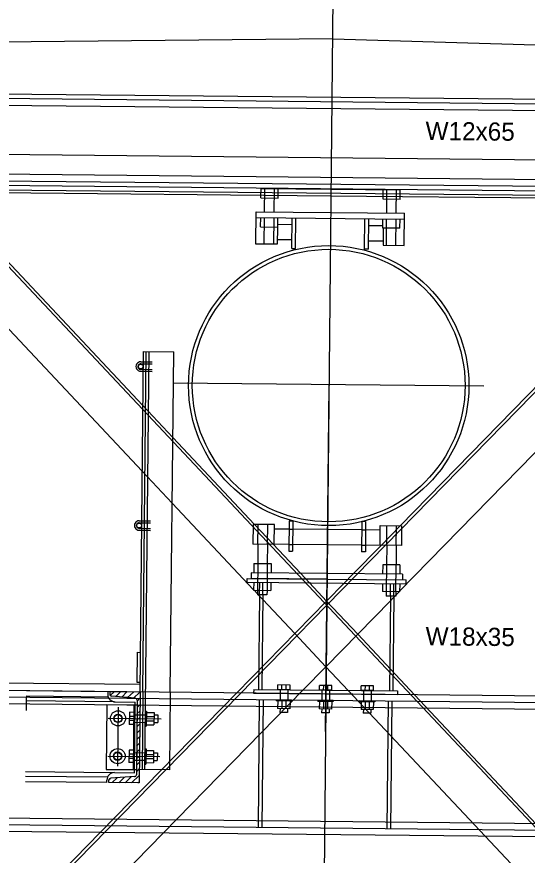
# Model space of a CAD drawing. Extents: x 632312 to 632885, y 378199 to 378534.
# Drawn here: x 632395.47 to 632401.08, y 378386.51 to 378395.75 of the extents above; entities that cross this region are included whole.
import ezdxf

# ---------------------------------------------------------------- set-up
doc = ezdxf.new("R2010")
doc.units = 0
for name, color, linetype in [('B_Boring', 7, 'Continuous'), ('B_Boring Annot', 7, 'Continuous'), ('R_Proposed Const Limits', 7, 'Continuous'), ('R_Proposed Const Limits Cut', 7, 'Continuous'), ('R_Road Edge of Shoulder', 7, 'Continuous'), ('R_Wall', 7, 'Continuous'), ('SHT_Dimensions', 7, 'Continuous')]:
    doc.layers.add(name, color=color, linetype=linetype)

msp = doc.modelspace()

# ---------------------------------------------------------------- linework, layer by layer
at = {"layer": 'B_Boring'}
for p, q in [((632404.4301, 378394.7533), (632393.4306, 378394.8626)), ((632404.4306, 378394.8037), (632393.4311, 378394.913)), ((632404.421, 378393.8458), (632393.4216, 378393.9552)), ((632404.4205, 378393.7954), (632393.4211, 378393.9048)), ((632398.1539, 378393.7504), (632398.1549, 378393.8577)), ((632399.6866, 378393.8352), (632398.1549, 378393.8505)), ((632398.1945, 378393.5973), (632398.1971, 378393.8573)), ((632398.2993, 378393.5962), (632398.3019, 378393.8562)), ((632398.343, 378393.7485), (632398.3441, 378393.8558)), ((632394.3786, 378393.8192), (632398.9201, 378393.7741)), ((632398.9201, 378393.7741), (632403.4615, 378393.7289)), ((632399.4965, 378393.737), (632399.4975, 378393.8443)), ((632399.5371, 378393.5839), (632399.5397, 378393.8439)), ((632399.6419, 378393.5829), (632399.6445, 378393.8429)), ((632399.6856, 378393.7351), (632399.6867, 378393.8425)), ((632398.1539, 378393.7504), (632398.343, 378393.7485)), ((632399.6856, 378393.7351), (632399.4965, 378393.737)), ((632398.0985, 378393.2433), (632398.102, 378393.5982)), ((632398.102, 378393.5982), (632399.7345, 378393.582)), ((632399.7309, 378393.2271), (632399.7345, 378393.582)), ((632398.1014, 378393.535), (632399.7338, 378393.5188)), ((632398.1507, 378393.4324), (632398.1517, 378393.5345)), ((632398.191, 378393.2424), (632398.1939, 378393.5341)), ((632398.2958, 378393.2413), (632398.2987, 378393.533)), ((632398.3399, 378393.4305), (632398.3409, 378393.5326)), ((632398.4929, 378393.1953), (632398.4963, 378393.5311)), ((632398.534, 378393.1949), (632398.5373, 378393.5307)), ((632399.2945, 378393.1873), (632399.2978, 378393.5231)), ((632399.3356, 378393.1869), (632399.3389, 378393.5227)), ((632399.4933, 378393.419), (632399.4943, 378393.5212)), ((632399.5336, 378393.229), (632399.5365, 378393.5207)), ((632399.6384, 378393.228), (632399.6413, 378393.5197)), ((632399.6825, 378393.4171), (632399.6835, 378393.5193)), ((632398.1507, 378393.4324), (632398.3399, 378393.4305)), ((632398.3345, 378393.4305), (632398.3326, 378393.241)), ((632398.4955, 378393.4561), (632398.3401, 378393.4577)), ((632399.3382, 378393.4478), (632399.4936, 378393.4462)), ((632399.6825, 378393.4171), (632399.4933, 378393.419)), ((632399.4987, 378393.419), (632399.4968, 378393.2294)), ((632398.3326, 378393.241), (632398.0985, 378393.2433)), ((632398.4939, 378393.2882), (632398.3331, 378393.2898)), ((632399.3365, 378393.2798), (632399.4973, 378393.2782)), ((632399.4968, 378393.2294), (632399.7309, 378393.2271)), ((632398.4929, 378393.1953), (632398.534, 378393.1949)), ((632399.3356, 378393.1869), (632399.2945, 378393.1873)), ((632396.824, 378388.3108), (632396.8613, 378392.0606)), ((632396.8552, 378388.3105), (632396.8925, 378392.0603)), ((632396.8613, 378392.0606), (632397.1946, 378392.0573)), ((632397.1573, 378388.3075), (632397.1946, 378392.0573)), ((632396.8323, 378391.9255), (632396.9573, 378391.9243)), ((632396.8325, 378391.9463), (632396.9575, 378391.9451)), ((632396.8314, 378391.8422), (632396.9564, 378391.8409)), ((632396.8316, 378391.863), (632396.9566, 378391.8618)), ((632398.0678, 378390.1571), (632398.0656, 378389.9404)), ((632398.3019, 378390.1548), (632398.0678, 378390.1571)), ((632398.2998, 378389.938), (632398.3019, 378390.1548)), ((632398.4631, 378390.1973), (632398.4598, 378389.8615)), ((632398.4631, 378390.1973), (632398.5042, 378390.1969)), ((632398.5042, 378390.1969), (632398.5009, 378389.8611)), ((632399.2647, 378390.1893), (632399.2614, 378389.8535)), ((632399.3058, 378390.1889), (632399.2647, 378390.1893)), ((632399.3058, 378390.1889), (632399.3024, 378389.8531)), ((632398.4622, 378390.1044), (632398.3014, 378390.106)), ((632399.2638, 378390.0965), (632398.5033, 378390.104)), ((632399.4656, 378390.0944), (632399.3048, 378390.096)), ((632399.464, 378389.9265), (632399.4661, 378390.1432)), ((632399.4661, 378390.1432), (632399.7002, 378390.1409)), ((632399.7002, 378390.1409), (632399.6981, 378389.9241)), ((632398.4605, 378389.9364), (632398.0656, 378389.9404)), ((632398.1212, 378389.9398), (632398.119, 378389.7263)), ((632398.226, 378389.9388), (632398.2238, 378389.7253)), ((632399.2621, 378389.9285), (632398.5016, 378389.936)), ((632399.6981, 378389.9241), (632399.3032, 378389.9281)), ((632399.5378, 378389.9257), (632399.5356, 378389.7122)), ((632399.6426, 378389.9247), (632399.6404, 378389.7112)), ((632398.4598, 378389.8615), (632398.5009, 378389.8611)), ((632399.3024, 378389.8531), (632399.2614, 378389.8535)), ((632398.0768, 378389.7267), (632398.0758, 378389.6246)), ((632398.0768, 378389.7267), (632398.266, 378389.7248)), ((632398.266, 378389.7248), (632398.265, 378389.6227)), ((632399.4934, 378389.7126), (632399.4924, 378389.6105)), ((632399.6826, 378389.7108), (632399.4934, 378389.7126)), ((632399.6826, 378389.7108), (632399.6816, 378389.6086)), ((632398.0454, 378389.6249), (632398.0448, 378389.5617)), ((632399.712, 378389.6083), (632398.0454, 378389.6249)), ((632399.712, 378389.6083), (632399.7114, 378389.5451)), ((632398.0027, 378389.5205), (632398.0031, 378389.5622)), ((632398.0027, 378389.5205), (632399.7526, 378389.5031)), ((632398.0031, 378389.5621), (632399.753, 378389.5447)), ((632398.0748, 378389.5197), (632398.0739, 378389.4317)), ((632398.264, 378389.5179), (632398.2631, 378389.4298)), ((632399.7526, 378389.5031), (632399.753, 378389.5448)), ((632398.0739, 378389.4317), (632398.2631, 378389.4298)), ((632398.1161, 378389.4313), (632398.1156, 378389.3823)), ((632398.2209, 378389.4302), (632398.2204, 378389.3812)), ((632399.4914, 378389.5057), (632399.4905, 378389.4176)), ((632399.6797, 378389.4157), (632399.4905, 378389.4176)), ((632399.5327, 378389.4172), (632399.5322, 378389.3682)), ((632399.6375, 378389.4162), (632399.637, 378389.3671)), ((632399.6806, 378389.5038), (632399.6797, 378389.4157)), ((632398.2204, 378389.3812), (632398.1156, 378389.3823)), ((632398.1388, 378389.382), (632398.1285, 378388.3395)), ((632398.1743, 378389.3817), (632398.1639, 378388.3392)), ((632399.637, 378389.3671), (632399.5322, 378389.3682)), ((632399.5784, 378389.3677), (632399.568, 378388.3252)), ((632399.6138, 378389.3674), (632399.6034, 378388.3249)), ((632396.7938, 378388.4153), (632396.7971, 378388.7486)), ((632396.7971, 378388.7486), (632396.8283, 378388.7483)), ((632396.8248, 378388.3942), (632394.3249, 378388.419)), ((632396.825, 378388.415), (632396.7938, 378388.4153)), ((632404.3653, 378388.2359), (632393.3658, 378388.3452)), ((632396.4692, 378388.3144), (632395.5741, 378388.3233)), ((632396.4692, 378388.3144), (632396.4689, 378388.2873)), ((632396.4907, 378388.3141), (632396.4904, 378388.287)), ((632396.824, 378388.3108), (632396.4907, 378388.3141)), ((632396.4964, 378388.2722), (632396.5387, 378388.3137)), ((632396.5573, 378388.2619), (632396.6094, 378388.313)), ((632396.6227, 378388.256), (632396.6801, 378388.3123)), ((632396.6881, 378388.2501), (632396.7508, 378388.3116)), ((632396.7535, 378388.2442), (632396.8215, 378388.3109)), ((632396.824, 378388.3108), (632396.814, 378387.3109)), ((632398.0743, 378388.3401), (632398.0739, 378388.2984)), ((632398.0743, 378388.3401), (632399.6576, 378388.3243)), ((632398.3399, 378388.3374), (632398.3405, 378388.3895)), ((632398.4753, 378388.3361), (632398.3399, 378388.3374)), ((632398.4759, 378388.3882), (632398.3405, 378388.3895)), ((632398.366, 378388.3372), (632398.3648, 378388.223)), ((632398.3851, 378388.337), (632398.3856, 378388.3891)), ((632398.4302, 378388.3365), (632398.4307, 378388.3886)), ((632398.4493, 378388.3363), (632398.4482, 378388.2222)), ((632398.4753, 378388.3361), (632398.4759, 378388.3882)), ((632398.7983, 378388.3329), (632398.7988, 378388.3849)), ((632398.9336, 378388.3315), (632398.7983, 378388.3329)), ((632398.9342, 378388.3836), (632398.7988, 378388.3849)), ((632398.8243, 378388.3326), (632398.8231, 378388.2184)), ((632398.8434, 378388.3324), (632398.8439, 378388.3845)), ((632398.8885, 378388.332), (632398.889, 378388.3841)), ((632398.9076, 378388.3318), (632398.9065, 378388.2176)), ((632398.9336, 378388.3315), (632398.9342, 378388.3836)), ((632399.2566, 378388.3283), (632399.2571, 378388.3804)), ((632399.392, 378388.327), (632399.2566, 378388.3283)), ((632399.3925, 378388.379), (632399.2571, 378388.3804)), ((632399.2826, 378388.3281), (632399.2815, 378388.2139)), ((632399.3017, 378388.3279), (632399.3022, 378388.3799)), ((632399.3468, 378388.3274), (632399.3473, 378388.3795)), ((632399.3659, 378388.3272), (632399.3648, 378388.2131)), ((632399.392, 378388.327), (632399.3925, 378388.379)), ((632399.6576, 378388.3243), (632399.6571, 378388.2826)), ((632404.3645, 378388.1634), (632393.3651, 378388.2727)), ((632395.5733, 378388.2508), (632395.5719, 378388.1065)), ((632396.4747, 378388.256), (632395.5735, 378388.2649)), ((632396.7716, 378388.2426), (632396.511, 378388.266)), ((632396.7922, 378388.2216), (632396.7841, 378387.4007)), ((632396.7922, 378388.2121), (632396.8233, 378388.2426)), ((632398.0739, 378388.2984), (632399.6571, 378388.2827)), ((632398.3232, 378388.2234), (632398.3231, 378388.213)), ((632398.4898, 378388.2218), (632398.3232, 378388.2234)), ((632398.4898, 378388.2218), (632398.4897, 378388.2113)), ((632398.7815, 378388.2189), (632398.7814, 378388.2084)), ((632398.9481, 378388.2172), (632398.7815, 378388.2189)), ((632398.9481, 378388.2172), (632398.948, 378388.2068)), ((632396.4584, 378388.1686), (632396.4513, 378387.4603)), ((632396.7917, 378388.1653), (632396.4584, 378388.1686)), ((632396.5514, 378388.2031), (632396.7712, 378388.2009)), ((632396.7534, 378387.4573), (632396.7605, 378388.1656)), ((632396.7635, 378387.4218), (632396.7712, 378388.2009)), ((632396.7917, 378388.1653), (632396.7846, 378387.457)), ((632396.7914, 378388.1413), (632396.8226, 378388.1719)), ((632398.4897, 378388.2113), (632398.3231, 378388.213)), ((632398.3387, 378388.2128), (632398.3379, 378388.1295)), ((632398.4733, 378388.1282), (632398.3379, 378388.1295)), ((632398.3639, 378388.1293), (632398.3635, 378388.0876)), ((632398.3838, 378388.2124), (632398.383, 378388.1291)), ((632398.429, 378388.212), (632398.4281, 378388.1286)), ((632398.4472, 378388.1284), (632398.4468, 378388.0868)), ((632398.4741, 378388.2115), (632398.4733, 378388.1282)), ((632398.948, 378388.2068), (632398.7814, 378388.2084)), ((632398.797, 378388.2083), (632398.7962, 378388.125)), ((632398.9316, 378388.1236), (632398.7962, 378388.125)), ((632398.8222, 378388.1247), (632398.8218, 378388.083)), ((632398.8421, 378388.2078), (632398.8413, 378388.1245)), ((632398.8873, 378388.2074), (632398.8864, 378388.1241)), ((632398.9055, 378388.1239), (632398.9051, 378388.0822)), ((632398.9324, 378388.2069), (632398.9316, 378388.1236)), ((632399.2398, 378388.2143), (632399.2397, 378388.2039)), ((632399.4063, 378388.2022), (632399.2397, 378388.2039)), ((632399.4065, 378388.2126), (632399.2398, 378388.2143)), ((632399.2553, 378388.2037), (632399.2545, 378388.1204)), ((632399.3005, 378388.2033), (632399.2996, 378388.12)), ((632399.3456, 378388.2028), (632399.3448, 378388.1195)), ((632399.3907, 378388.2024), (632399.3899, 378388.1191)), ((632399.4065, 378388.2126), (632399.4063, 378388.2022)), ((632396.7076, 378388.088), (632396.7063, 378387.9526)), ((632396.7593, 378388.0424), (632396.7072, 378388.0429)), ((632396.7597, 378388.0875), (632396.7076, 378388.088)), ((632396.7597, 378388.0875), (632396.7584, 378387.9521)), ((632396.7907, 378388.0706), (632396.8219, 378388.1012)), ((632396.8844, 378388.1019), (632396.8827, 378387.9352)), ((632396.8844, 378388.1019), (632396.8948, 378388.1018)), ((632396.8948, 378388.1018), (632396.8932, 378387.9351)), ((632396.8942, 378388.041), (632396.9775, 378388.0402)), ((632396.8947, 378388.0861), (632396.978, 378388.0853)), ((632396.978, 378388.0853), (632396.9766, 378387.9499)), ((632396.9777, 378388.0593), (632397.0194, 378388.0589)), ((632397.0194, 378388.0589), (632397.0186, 378387.9755)), ((632398.4468, 378388.0868), (632398.3635, 378388.0876)), ((632398.9051, 378388.0822), (632398.8218, 378388.083)), ((632399.3899, 378388.1191), (632399.2545, 378388.1204)), ((632399.2805, 378388.1201), (632399.2801, 378388.0785)), ((632399.3634, 378388.0777), (632399.2801, 378388.0785)), ((632399.3639, 378388.1193), (632399.3634, 378388.0777)), ((632396.7584, 378387.9521), (632396.7063, 378387.9526)), ((632396.7588, 378387.9972), (632396.7067, 378387.9977)), ((632396.7893, 378387.9292), (632396.8205, 378387.9598)), ((632396.79, 378387.9999), (632396.8212, 378388.0305)), ((632396.8933, 378387.9508), (632396.9766, 378387.9499)), ((632396.8938, 378387.9959), (632396.9771, 378387.9951)), ((632396.9769, 378387.976), (632397.0186, 378387.9755)), ((632396.7886, 378387.8585), (632396.8198, 378387.889)), ((632396.8827, 378387.9352), (632396.8932, 378387.9351)), ((632396.7879, 378387.7878), (632396.8191, 378387.8183)), ((632396.7035, 378387.6714), (632396.7021, 378387.536)), ((632396.7556, 378387.6708), (632396.7035, 378387.6714)), ((632396.7556, 378387.6708), (632396.7542, 378387.5355)), ((632396.7865, 378387.6464), (632396.8177, 378387.6769)), ((632396.7872, 378387.7171), (632396.8184, 378387.7476)), ((632396.8803, 378387.6852), (632396.8786, 378387.5186)), ((632396.8803, 378387.6852), (632396.8907, 378387.6851)), ((632396.8907, 378387.6851), (632396.889, 378387.5185)), ((632396.8905, 378387.6695), (632396.9738, 378387.6687)), ((632396.9738, 378387.6687), (632396.9725, 378387.5333)), ((632396.7547, 378387.5806), (632396.7026, 378387.5811)), ((632396.7551, 378387.6257), (632396.703, 378387.6262)), ((632396.7858, 378387.5757), (632396.817, 378387.6062)), ((632396.8896, 378387.5792), (632396.9729, 378387.5784)), ((632396.8901, 378387.6244), (632396.9734, 378387.6235)), ((632396.9736, 378387.6426), (632397.0152, 378387.6422)), ((632397.0152, 378387.6422), (632397.0144, 378387.5589)), ((632396.7542, 378387.5355), (632396.7021, 378387.536)), ((632396.7851, 378387.505), (632396.8163, 378387.5355)), ((632396.8786, 378387.5186), (632396.889, 378387.5185)), ((632396.8892, 378387.5341), (632396.9725, 378387.5333)), ((632396.9728, 378387.5593), (632397.0144, 378387.5589)), ((632396.4513, 378387.4603), (632396.7847, 378387.457)), ((632396.5437, 378387.424), (632396.7635, 378387.4218)), ((632396.7308, 378387.3117), (632396.8149, 378387.3941)), ((632396.7844, 378387.4343), (632396.8156, 378387.4648)), ((632396.4593, 378387.3144), (632395.5641, 378387.3233)), ((632396.4659, 378387.3727), (632395.5647, 378387.3816)), ((632396.4593, 378387.3144), (632396.4595, 378387.3415)), ((632396.4807, 378387.3142), (632396.481, 378387.3413)), ((632396.814, 378387.3109), (632396.4807, 378387.3142)), ((632396.814, 378387.3109), (632396.4807, 378387.3142)), ((632396.4822, 378387.348), (632396.4952, 378387.3608)), ((632396.7631, 378387.3801), (632396.502, 378387.3619)), ((632396.5187, 378387.3138), (632396.5728, 378387.3668)), ((632396.5894, 378387.3131), (632396.6497, 378387.3722)), ((632396.6601, 378387.3124), (632396.7266, 378387.3776)), ((632396.8015, 378387.311), (632396.8142, 378387.3234)), ((632396.8109, 378387.3109), (632396.8141, 378387.314)), ((632404.3506, 378386.7584), (632393.3511, 378386.8678)), ((632404.3499, 378386.6859), (632393.3504, 378386.7953))]:
    msp.add_line(p, q, dxfattribs=at)
for points in [[(632396.8481, 378390.7422), (632394.3742, 378393.378), (632394.7388, 378393.7202), (632396.8553, 378391.4652)], [(632399.6797, 378389.4202), (632403.4571, 378393.2877), (632403.0994, 378393.6371), (632399.6849, 378390.1411)], [(632397.1852, 378391.1137), (632398.0831, 378390.157)], [(632398.074, 378389.4362), (632397.178, 378390.3908)], [(632398.2886, 378389.9381), (632398.5876, 378389.6195)], [(632399.4752, 378389.9263), (632399.1598, 378389.6034)], [(632399.0684, 378389.5099), (632398.8757, 378389.3126), (632397.887, 378388.3003)], [(632398.687, 378389.5137), (632398.8757, 378389.3126)], [(632398.1157, 378389.3917), (632398.0782, 378389.4317)], [(632399.6371, 378389.3766), (632399.6754, 378389.4158)], [(632398.1387, 378389.3672), (632398.1246, 378389.3822)], [(632398.526, 378388.9545), (632398.1737, 378389.3298)], [(632399.6136, 378389.3525), (632399.628, 378389.3672)], [(632398.6195, 378388.3346), (632398.8685, 378388.5896), (632399.5778, 378389.3159)], [(632399.2182, 378388.9476), (632399.8441, 378388.2808)], [(632399.1124, 378388.3297), (632398.8685, 378388.5896)], [(632396.3876, 378386.7651), (632394.2871, 378384.6144)], [(632394.6448, 378384.2651), (632397.0798, 378386.7582)], [(632403.0054, 378384.182), (632400.6204, 378386.723)]]:
    msp.add_lwpolyline(points, dxfattribs=at)
for centre, radius in [((632398.8993, 378391.6851), 1.5417), ((632398.8993, 378391.6851), 1.5), ((632396.5819, 378388.0216), 0.0469), ((632396.5778, 378387.6049), 0.0469)]:
    msp.add_circle(centre, radius, dxfattribs=at)
for centre, radius, start, end in [((632396.832, 378391.8943), 0.0521, 89.43036, 269.43036), ((632396.832, 378391.8943), 0.0312, 89.43036, 269.43036), ((632396.5523, 378388.2865), 0.0833, 179.43036, 269.43036), ((632396.5112, 378388.2868), 0.0208, 179.4219, 269.43036), ((632396.7714, 378388.2218), 0.0208, 359.43036, 89.43036), ((632396.5429, 378387.3407), 0.0833, 89.43036, 179.43036), ((632396.7633, 378387.4009), 0.0208, 269.43036, 359.43036), ((632396.5018, 378387.3411), 0.0208, 89.43036, 179.43036)]:
    msp.add_arc(centre, radius, start, end, dxfattribs=at)
at = {"layer": 'B_Boring Annot'}
for q in [(632394.9931, 378395.4626), (632402.8939, 378395.3841)]:
    msp.add_line((632398.9443, 378395.5024), q, dxfattribs=at)
at = {"layer": 'R_Proposed Const Limits'}
msp.add_arc((632396.5523, 378388.2865), 0.0833, 179.43036, 269.43036, dxfattribs=at)
at = {"layer": 'R_Proposed Const Limits Cut'}
for p, q in [((632404.4293, 378394.6787), (632393.4299, 378394.7881)), ((632403.4656, 378394.1456), (632394.3828, 378394.2359)), ((632404.4218, 378393.9204), (632393.4223, 378394.0298)), ((632403.4618, 378393.755), (632394.3789, 378393.8453)), ((632394.716, 378393.6988), (632403.3472, 378384.5027)), ((632403.1218, 378393.6153), (632394.3094, 378384.5926)), ((632396.878, 378387.4561), (632396.9237, 378392.06)), ((632396.8553, 378391.4652), (632397.1852, 378391.1137)), ((632396.8481, 378390.7422), (632397.178, 378390.3908)), ((632398.2897, 378389.9381), (632398.0831, 378390.157)), ((632398.1212, 378389.9398), (632398.1233, 378390.1566)), ((632398.226, 378389.9388), (632398.2281, 378390.1556)), ((632398.4622, 378390.1044), (632398.5033, 378390.104)), ((632399.2638, 378390.0965), (632399.3048, 378390.096)), ((632399.4752, 378389.9263), (632399.6849, 378390.1411)), ((632399.5378, 378389.9257), (632399.5399, 378390.1425)), ((632399.6426, 378389.9247), (632399.6447, 378390.1415)), ((632398.4605, 378389.9364), (632398.5016, 378389.936)), ((632399.2621, 378389.9285), (632399.3032, 378389.9281)), ((632398.119, 378389.7263), (632398.1161, 378389.4313)), ((632398.2238, 378389.7253), (632398.2209, 378389.4302)), ((632399.5356, 378389.7122), (632399.5327, 378389.4172)), ((632399.6375, 378389.4162), (632399.6404, 378389.7112)), ((632398.687, 378389.5137), (632398.5876, 378389.6195)), ((632399.0684, 378389.5099), (632399.1598, 378389.6034)), ((632398.1388, 378389.382), (632398.1402, 378389.5191)), ((632398.1743, 378389.3817), (632398.1756, 378389.5187)), ((632398.074, 378389.4362), (632398.0782, 378389.4317)), ((632399.5784, 378389.3677), (632399.5797, 378389.5048)), ((632399.6138, 378389.3674), (632399.6151, 378389.5044)), ((632399.6754, 378389.4158), (632399.6797, 378389.4202)), ((632398.1157, 378389.3917), (632398.1246, 378389.3822)), ((632398.1387, 378389.3672), (632398.1737, 378389.3298)), ((632399.5778, 378389.3159), (632399.6136, 378389.3525)), ((632399.628, 378389.3672), (632399.6371, 378389.3766)), ((632399.2182, 378388.9476), (632398.8757, 378389.3126)), ((632398.526, 378388.9545), (632398.8685, 378388.5896)), ((632396.8552, 378388.3105), (632396.8467, 378387.4564)), ((632397.0798, 378386.7582), (632398.6195, 378388.3346)), ((632399.1124, 378388.3297), (632400.6204, 378386.723)), ((632397.887, 378388.3003), (632396.3876, 378386.7651)), ((632397.1573, 378388.3075), (632397.1488, 378387.4534)), ((632399.8441, 378388.2808), (632401.3126, 378386.7161)), ((632404.3638, 378388.09), (632393.3644, 378388.1994)), ((632396.5384, 378388.2043), (632395.573, 378388.2139)), ((632396.7595, 378388.0615), (632396.884, 378388.0602)), ((632396.7586, 378387.9781), (632396.8832, 378387.9769)), ((632396.7553, 378387.6448), (632396.8798, 378387.6436)), ((632396.7545, 378387.5615), (632396.879, 378387.5602)), ((632396.5306, 378387.4231), (632395.5652, 378387.4327)), ((632397.1488, 378387.4534), (632396.8155, 378387.4567)), ((632404.3513, 378386.8318), (632393.3518, 378386.9411))]:
    msp.add_line(p, q, dxfattribs=at)
for centre, radius in [((632396.5819, 378388.0216), 0.0833), ((632396.5819, 378388.0216), 0.0417), ((632396.5778, 378387.6049), 0.0833), ((632396.5778, 378387.6049), 0.0417)]:
    msp.add_circle(centre, radius, dxfattribs=at)
at = {"layer": 'R_Road Edge of Shoulder'}
msp.add_line((632398.7765, 378378.6227), (632399.1063, 378411.7996), dxfattribs=at)
at = {"layer": 'R_Wall'}
for p, q in [((632396.5831, 378388.1443), (632396.5767, 378387.4962)), ((632396.4726, 378388.0226), (632397.0585, 378388.0168)), ((632396.4695, 378387.606), (632397.0422, 378387.6003))]:
    msp.add_line(p, q, dxfattribs=at)
at = {"layer": 'SHT_Dimensions'}
for p, q in [((632397.1837, 378391.7162), (632400.6042, 378391.6822)), ((632398.8993, 378391.6887), (632398.8614, 378387.8771)), ((632396.8149, 378390.1756), (632396.9399, 378390.1744)), ((632396.8151, 378390.1964), (632396.9401, 378390.1952)), ((632396.814, 378390.0923), (632396.939, 378390.091)), ((632396.8142, 378390.1131), (632396.9392, 378390.1119)), ((632398.8781, 378389.5534), (632398.0448, 378389.5617)), ((632398.1357, 378388.2253), (632398.1217, 378386.8204)), ((632398.1773, 378388.2249), (632398.1634, 378386.8199)), ((632399.5523, 378388.2112), (632399.5383, 378386.8063)), ((632399.5939, 378388.2108), (632399.58, 378386.8059))]:
    msp.add_line(p, q, dxfattribs=at)
for centre in [(632396.832, 378391.8943), (632396.8146, 378390.1443)]:
    msp.add_circle(centre, 0.0261, dxfattribs=at)
for radius in [0.0521, 0.0312]:
    msp.add_arc((632396.8146, 378390.1443), radius, 89.43036, 269.43036, dxfattribs=at)

# ---------------------------------------------------------------- texts
for s, p in [('W12x65', (632399.9637, 378394.3895)), ('W18x35', (632399.964, 378388.8264))]:
    msp.add_text(s, height=0.2, rotation=359.43036, dxfattribs=at).set_placement(p)

doc.saveas('drawing.dxf')
